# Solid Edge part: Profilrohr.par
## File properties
Dokumentum tartalom típus: 0
Last saved by: ahadarics
Revision: 76
Sűrűség: 0,000 kg/m^3
Pontosság: 0,990
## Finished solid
Body 1: solid body, 6 faces, 6 edges, 0 vertices.
  Faces by surface: cone 2, cylinder 2, plane 2
  Edges by curve: circle 6
Bounding box of the edges (mm): 11.270 x 11.270 x 35.500, from (-5.635, -5.635, -17.75) to (5.635, 5.635, 17.75).
Cylindrical faces by radius (mm): R5 x1, R5.635 x1
Conical faces (half-angle, radius in mm at the cone's reference point): 15 deg R5.067 x2
Planar faces by outward normal: +z 1, -z 1
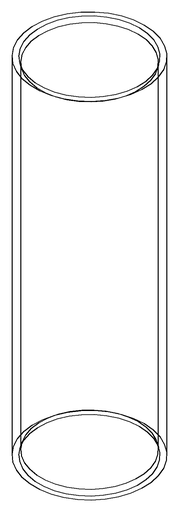
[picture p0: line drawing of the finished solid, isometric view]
